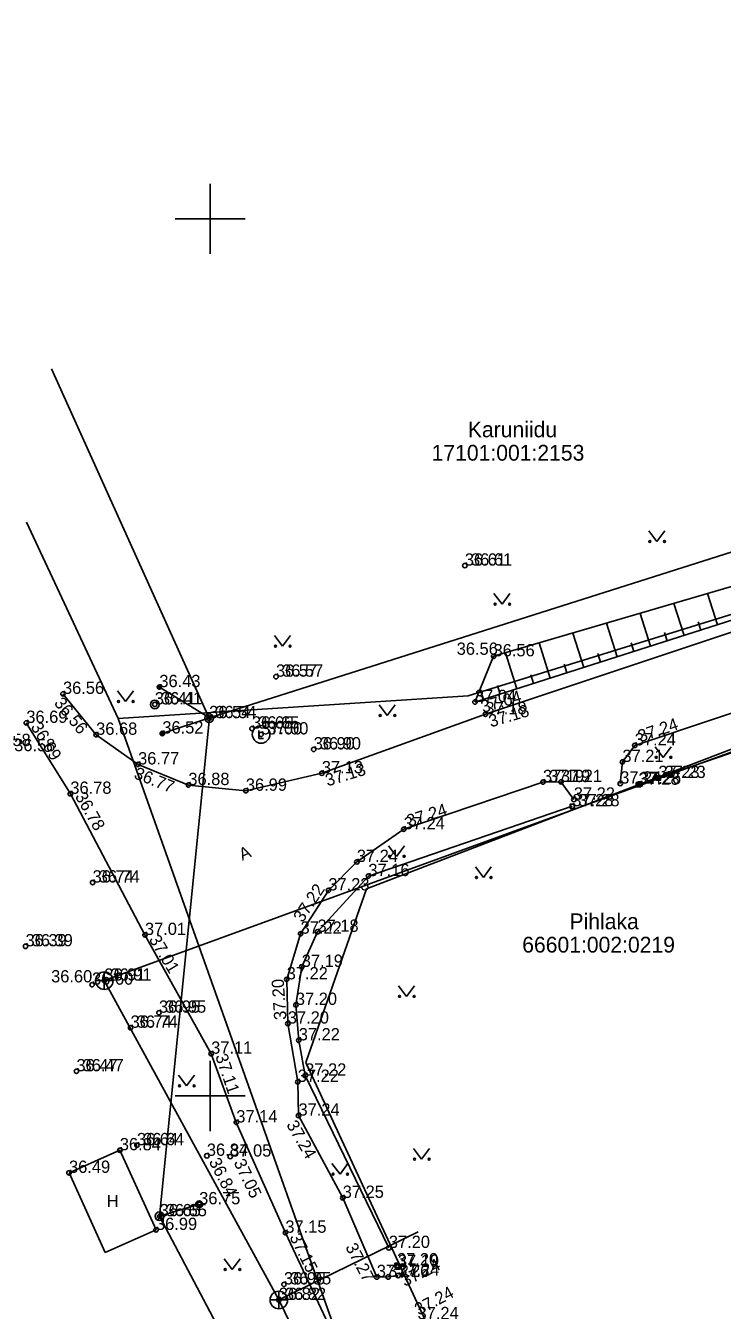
# Model space of a CAD drawing. Extents: x 627548 to 628052, y 6467984 to 6468802.
# Drawn here: x 627639.5 to 627679.2, y 6468387.8 to 6468461 of the extents above; entities that cross this region are included whole.
import ezdxf

# ---------------------------------------------------------------- set-up
doc = ezdxf.new("R2010")
doc.units = 0
for name, color, linetype in [('AED', 7, 'Continuous'), ('HALJASTUS', 7, 'Continuous'), ('KAEV', 7, 'Continuous'), ('KKAEV', 7, 'Continuous'), ('KORGUS-EH2000', 7, 'Continuous'), ('KTRASS', 7, 'Continuous'), ('MOOTKORG-EH2000', 7, 'Continuous'), ('MOOTMPUNKT', 7, 'Continuous'), ('MPOHULIIN', 7, 'Continuous'), ('PIIR', 7, 'Continuous'), ('POST', 7, 'Continuous'), ('RAJATIS', 7, 'Continuous'), ('RELJEEF', 7, 'Continuous'), ('SIOHULIIN', 7, 'Continuous'), ('TEE', 7, 'Continuous'), ('VORK', 7, 'Continuous')]:
    doc.layers.add(name, color=color, linetype=linetype)

msp = doc.modelspace()

# ---------------------------------------------------------------- linework, layer by layer
at = {"layer": 'AED'}
for p, q in [((627674.27, 6468417.863), (627674.27, 6468417.613)), ((627674.27, 6468417.863), (627674.52, 6468417.863)), ((627674.357, 6468417.911), (627674.357, 6468417.661)), ((627674.357, 6468417.911), (627674.607, 6468417.911)), ((627674.52, 6468417.863), (627674.52, 6468417.613)), ((627674.607, 6468417.911), (627674.607, 6468417.661)), ((627675.406, 6468418.249), (627675.406, 6468417.999)), ((627675.406, 6468418.249), (627675.656, 6468418.249)), ((627675.406, 6468417.999), (627675.656, 6468417.999)), ((627675.656, 6468418.249), (627675.656, 6468417.999)), ((627674.27, 6468417.613), (627674.52, 6468417.613)), ((627674.357, 6468417.661), (627674.607, 6468417.661)), ((627670.5, 6468416.637), (627670.5, 6468416.387)), ((627670.5, 6468416.637), (627670.75, 6468416.637)), ((627670.5, 6468416.387), (627670.75, 6468416.387)), ((627670.75, 6468416.637), (627670.75, 6468416.387)), ((627660.516, 6468390.467), (627660.516, 6468390.217)), ((627660.516, 6468390.467), (627660.766, 6468390.467)), ((627660.516, 6468390.217), (627660.766, 6468390.217)), ((627660.568, 6468390.378), (627660.568, 6468390.128)), ((627660.568, 6468390.378), (627660.818, 6468390.378)), ((627660.568, 6468390.128), (627660.818, 6468390.128)), ((627660.766, 6468390.467), (627660.766, 6468390.217)), ((627660.818, 6468390.378), (627660.818, 6468390.128))]:
    msp.add_line(p, q, dxfattribs=at)
for points in [[(627699.286, 6468421.733), (627697.85, 6468425.664), (627684.125, 6468421.07), (627675.531, 6468418.124)], [(627670.625, 6468416.512), (627659.01, 6468412.531), (627656.111, 6468409.355), (627655.215, 6468407.357), (627654.88, 6468405.188), (627655.043, 6468403.167), (627655.409, 6468401.157), (627660.175, 6468391.332)]]:
    msp.add_lwpolyline(points, dxfattribs=at)
at = {"layer": 'HALJASTUS'}
for p, q in [((627674.982, 6468432.212), (627675.445, 6468431.605)), ((627675.445, 6468431.605), (627675.891, 6468432.212)), ((627666.165, 6468428.636), (627666.628, 6468428.029)), ((627666.628, 6468428.029), (627667.074, 6468428.636)), ((627653.655, 6468426.252), (627654.118, 6468425.645)), ((627654.118, 6468425.645), (627654.564, 6468426.252)), ((627644.719, 6468423.093), (627645.182, 6468422.486)), ((627645.182, 6468422.486), (627645.628, 6468423.093)), ((627659.621, 6468422.293), (627660.084, 6468421.686)), ((627660.084, 6468421.686), (627660.53, 6468422.293)), ((627675.348, 6468419.909), (627675.811, 6468419.302)), ((627675.811, 6468419.302), (627676.257, 6468419.909)), ((627660.156, 6468414.265), (627660.619, 6468413.658)), ((627660.619, 6468413.658), (627661.064, 6468414.265)), ((627665.104, 6468413.054), (627665.567, 6468412.447)), ((627665.567, 6468412.447), (627666.013, 6468413.054)), ((627660.725, 6468406.283), (627661.188, 6468405.676)), ((627661.188, 6468405.676), (627661.634, 6468406.283)), ((627648.193, 6468401.183), (627648.656, 6468400.576)), ((627648.656, 6468400.576), (627649.102, 6468401.183)), ((627661.578, 6468397.008), (627662.041, 6468396.401)), ((627662.041, 6468396.401), (627662.487, 6468397.008)), ((627656.934, 6468396.144), (627657.397, 6468395.537)), ((627657.397, 6468395.537), (627657.843, 6468396.144)), ((627650.792, 6468390.714), (627651.256, 6468390.107)), ((627651.256, 6468390.107), (627651.701, 6468390.714))]:
    msp.add_line(p, q, dxfattribs=at)
for centre in [(627675.044, 6468431.605), (627675.873, 6468431.605), (627666.227, 6468428.029), (627667.056, 6468428.029), (627653.717, 6468425.645), (627654.546, 6468425.645), (627644.781, 6468422.486), (627645.61, 6468422.486), (627659.683, 6468421.686), (627660.512, 6468421.686), (627675.41, 6468419.302), (627676.239, 6468419.302), (627660.218, 6468413.658), (627661.047, 6468413.658), (627665.166, 6468412.447), (627665.995, 6468412.447), (627660.787, 6468405.676), (627661.616, 6468405.676), (627648.255, 6468400.576), (627649.084, 6468400.576), (627661.64, 6468396.401), (627662.469, 6468396.401), (627656.996, 6468395.537), (627657.825, 6468395.537), (627650.855, 6468390.107), (627651.683, 6468390.107)]:
    msp.add_circle(centre, 0.055, dxfattribs=at)
at = {"layer": 'KAEV'}
for p, q in [((627652.769, 6468420.834), (627652.769, 6468420.384)), ((627652.769, 6468420.384), (627653.027, 6468420.384))]:
    msp.add_line(p, q, dxfattribs=at)
msp.add_circle((627652.898, 6468420.609), 0.5, dxfattribs=at)
at = {"layer": 'KKAEV'}
for p, q in [((627643.967, 6468406.071), (627643.967, 6468407.071)), ((627643.467, 6468406.571), (627644.467, 6468406.571)), ((627653.907, 6468387.868), (627653.907, 6468388.868)), ((627653.407, 6468388.368), (627654.407, 6468388.368))]:
    msp.add_line(p, q, dxfattribs=at)
for centre in [(627643.967, 6468406.571), (627653.907, 6468388.368)]:
    msp.add_circle(centre, 0.5, dxfattribs=at)
at = {"layer": 'KTRASS'}
for points in [[(627653.907, 6468388.368), (627643.967, 6468406.571), (627696.734, 6468425.803), (627727.929, 6468434.638), (627765.976, 6468446.513), (627766.878, 6468443.315), (627768.149, 6468438.807)], [(627669.837, 6468355.594), (627653.907, 6468388.368), (627661.842, 6468392.243)]]:
    msp.add_lwpolyline(points, dxfattribs=at)
at = {"layer": 'MOOTMPUNKT'}
for centre in [(627664.503, 6468430.232), (627666.141, 6468425.06), (627653.747, 6468423.9), (627641.613, 6468422.918), (627647.103, 6468423.305), (627646.844, 6468422.319), (627665.082, 6468422.456), (627649.939, 6468421.535), (627665.677, 6468421.76), (627639.524, 6468421.265), (627643.502, 6468420.588), (627647.272, 6468420.66), (627652.378, 6468420.942), (627652.898, 6468420.609), (627674.185, 6468419.981), (627655.894, 6468419.753), (627645.892, 6468418.897), (627656.357, 6468418.393), (627673.482, 6468419.039), (627648.756, 6468417.722), (627668.955, 6468417.89), (627669.976, 6468417.9), (627673.355, 6468417.806), (627674.395, 6468417.738), (627674.482, 6468417.786), (627675.531, 6468418.124), (627642.033, 6468417.224), (627652.03, 6468417.397), (627670.625, 6468416.512), (627670.712, 6468416.891), (627661.021, 6468415.201), (627658.351, 6468413.337), (627659.01, 6468412.531), (627643.3, 6468412.165), (627656.73, 6468411.715), (627646.281, 6468409.175), (627655.147, 6468409.247), (627656.111, 6468409.355), (627639.481, 6468408.528), (627655.215, 6468407.357), (627643.271, 6468406.341), (627643.967, 6468406.571), (627654.357, 6468406.644), (627647.079, 6468404.744), (627654.88, 6468405.188), (627645.461, 6468403.886), (627654.421, 6468404.123), (627655.043, 6468403.167), (627650.055, 6468402.405), (627642.38, 6468401.404), (627655.409, 6468401.157), (627654.986, 6468400.8), (627655.028, 6468398.877), (627651.487, 6468398.488), (627645.827, 6468397.19), (627644.85, 6468396.901), (627649.807, 6468396.584), (627651.139, 6468396.541), (627641.957, 6468395.613), (627649.371, 6468393.822), (627657.549, 6468394.188), (627647.118, 6468393.14), (627646.912, 6468392.358), (627654.281, 6468392.2), (627660.175, 6468391.332), (627660.641, 6468390.342), (627660.693, 6468390.253), (627654.2, 6468389.254), (627659.49, 6468389.674), (627660.136, 6468389.678), (627660.706, 6468389.759), (627653.907, 6468388.368)]:
    msp.add_circle(centre, 0.125, dxfattribs=at)
at = {"layer": 'MPOHULIIN'}
msp.add_line((627649.939, 6468421.535), (627640.956, 6468441.442), dxfattribs=at)
for points in [[(627697.787, 6468436.749), (627649.965, 6468421.549)], [(627649.965, 6468421.549), (627647.118, 6468393.14)], [(627647.118, 6468393.14), (627668.977, 6468351.69)]]:
    msp.add_lwpolyline(points, dxfattribs=at)
at = {"layer": 'PIIR'}
for p, q in [((627644.75, 6468421.52), (627639.527, 6468432.704)), ((627696.02, 6468432.54), (627664.7, 6468422.8)), ((627658.9, 6468411.81), (627697.47, 6468426.57)), ((627664.7, 6468422.8), (627644.75, 6468421.52)), ((627664.45, 6468365.98), (627644.75, 6468421.52)), ((627655.45, 6468401.9), (627658.9, 6468411.81)), ((627668.1, 6468374.6), (627655.45, 6468401.9))]:
    msp.add_line(p, q, dxfattribs=at)
at = {"layer": 'POST'}
for points in [[(627647.103, 6468423.305), (627649.965, 6468421.549)], [(627647.272, 6468420.66), (627649.965, 6468421.549)], [(627649.371, 6468393.822), (627647.118, 6468393.14)]]:
    msp.add_lwpolyline(points, dxfattribs=at)
for centre, radius in [((627647.103, 6468423.305), 0.125), ((627647.103, 6468423.305), 0.117), ((627647.103, 6468423.305), 0.109), ((627647.103, 6468423.305), 0.102), ((627647.103, 6468423.305), 0.0938), ((627647.103, 6468423.305), 0.086), ((627647.103, 6468423.305), 0.0782), ((627647.103, 6468423.305), 0.0704), ((627647.103, 6468423.305), 0.0626), ((627647.103, 6468423.305), 0.0548), ((627647.103, 6468423.305), 0.047), ((627647.103, 6468423.305), 0.0392), ((627647.103, 6468423.305), 0.0314), ((627647.103, 6468423.305), 0.0236), ((627647.103, 6468423.305), 0.0158), ((627647.103, 6468423.305), 0.00798), ((627647.103, 6468423.305), 0.000186), ((627649.939, 6468421.535), 0.25), ((627649.939, 6468421.535), 0.0234), ((627647.272, 6468420.66), 0.125), ((627647.272, 6468420.66), 0.117), ((627647.272, 6468420.66), 0.109), ((627647.272, 6468420.66), 0.102), ((627647.272, 6468420.66), 0.0938), ((627647.272, 6468420.66), 0.086), ((627647.272, 6468420.66), 0.0782), ((627647.272, 6468420.66), 0.0704), ((627647.272, 6468420.66), 0.0626), ((627647.272, 6468420.66), 0.0548), ((627647.272, 6468420.66), 0.047), ((627647.272, 6468420.66), 0.0392), ((627647.272, 6468420.66), 0.0314), ((627647.272, 6468420.66), 0.0236), ((627647.272, 6468420.66), 0.0158), ((627647.272, 6468420.66), 0.00798), ((627647.272, 6468420.66), 0.000186), ((627649.371, 6468393.822), 0.2), ((627647.118, 6468393.14), 0.25), ((627647.118, 6468393.14), 0.0234)]:
    msp.add_circle(centre, radius, dxfattribs=at)
at = {"layer": 'RAJATIS'}
for points in [[(627646.912, 6468392.358), (627644.85, 6468396.901), (627641.957, 6468395.613)], [(627644.019, 6468391.07), (627641.957, 6468395.613)], [(627646.912, 6468392.358), (627644.019, 6468391.07)]]:
    msp.add_lwpolyline(points, dxfattribs=at)
msp.add_circle((627646.844, 6468422.319), 0.25, dxfattribs=at)
at = {"layer": 'RELJEEF'}
for p, q in [((627676.991, 6468426.255), (627676.411, 6468428.072)), ((627678.896, 6468426.863), (627678.331, 6468428.635)), ((627675.085, 6468425.647), (627674.491, 6468427.509)), ((627673.18, 6468425.039), (627672.572, 6468426.946)), ((627677.943, 6468426.559), (627677.791, 6468427.035)), ((627671.275, 6468424.432), (627670.652, 6468426.383)), ((627676.038, 6468425.951), (627675.886, 6468426.428)), ((627667.464, 6468423.216), (627666.813, 6468425.257)), ((627669.369, 6468423.824), (627668.732, 6468425.82)), ((627672.227, 6468424.735), (627672.075, 6468425.212)), ((627674.133, 6468425.343), (627673.981, 6468425.82)), ((627670.322, 6468424.128), (627670.17, 6468424.604)), ((627668.416, 6468423.52), (627668.264, 6468423.996)), ((627665.558, 6468422.608), (627665.376, 6468423.179)), ((627666.511, 6468422.912), (627666.359, 6468423.388))]:
    msp.add_line(p, q, dxfattribs=at)
for points in [[(627696.651, 6468435.326), (627694.06, 6468434.488), (627681.566, 6468429.584), (627666.141, 6468425.06), (627665.082, 6468422.456)], [(627665.082, 6468422.456), (627682.037, 6468427.865), (627695.156, 6468431.738), (627696.486, 6468433.552), (627696.651, 6468435.326)]]:
    msp.add_lwpolyline(points, dxfattribs=at)
at = {"layer": 'SIOHULIIN'}
for points in [[(627697.787, 6468436.749), (627649.965, 6468421.549)], [(627649.965, 6468421.549), (627647.118, 6468393.14)], [(627647.118, 6468393.14), (627668.977, 6468351.69)]]:
    msp.add_lwpolyline(points, dxfattribs=at)
at = {"layer": 'TEE'}
for points in [[(627796.263, 6468461.011), (627787.58, 6468457.698), (627775.784, 6468453.617), (627755.708, 6468445.797), (627743.362, 6468441.806), (627728.433, 6468436.983), (627717.465, 6468433.665), (627699.12, 6468428.233), (627696.098, 6468427.452), (627683.485, 6468423.1), (627674.185, 6468419.981), (627673.482, 6468419.039), (627673.355, 6468417.806)], [(627641.613, 6468422.918), (627643.502, 6468420.588), (627645.892, 6468418.897), (627648.756, 6468417.722), (627652.03, 6468417.397), (627656.357, 6468418.393), (627665.677, 6468421.76), (627682.248, 6468427.296), (627694.979, 6468431.122), (627698.392, 6468432.085), (627706.02, 6468434.537), (627706.299, 6468441.373)], [(627664.163, 6468372.339), (627656.73, 6468386.978), (627654.281, 6468392.2), (627651.487, 6468398.488), (627650.055, 6468402.405), (627646.281, 6468409.175), (627642.033, 6468417.224), (627639.524, 6468421.265)], [(627670.712, 6468416.891), (627669.976, 6468417.9), (627668.955, 6468417.89), (627661.021, 6468415.201), (627658.351, 6468413.337), (627656.73, 6468411.715), (627655.147, 6468409.247), (627654.357, 6468406.644), (627654.421, 6468404.123), (627654.986, 6468400.8), (627655.028, 6468398.877), (627657.549, 6468394.188), (627659.49, 6468389.674), (627660.136, 6468389.678), (627660.706, 6468389.759)]]:
    msp.add_lwpolyline(points, dxfattribs=at)
at = {"layer": 'VORK'}
for p, q in [((627650, 6468452), (627650, 6468448)), ((627648, 6468450), (627652, 6468450)), ((627650, 6468402), (627650, 6468398)), ((627648, 6468400), (627652, 6468400))]:
    msp.add_line(p, q, dxfattribs=at)

# ---------------------------------------------------------------- texts
at = {"layer": 'KORGUS-EH2000'}
for s, p in [('36.61', (627664.853, 6468430.232)), ('36.56', (627664.04, 6468425.147)), ('36.57', (627654.097, 6468423.9)), ('36.41', (627647.194, 6468422.319)), ('36.54', (627650.289, 6468421.535)), ('36.65', (627652.728, 6468420.942)), ('37.00', (627653.248, 6468420.609)), ('36.58', (627637.432, 6468419.944)), ('36.90', (627656.244, 6468419.753)), ('37.19', (627669.305, 6468417.89)), ('37.23', (627675.881, 6468418.124)), ('37.28', (627670.975, 6468416.512)), ('36.74', (627643.65, 6468412.165)), ('36.39', (627639.831, 6468408.528)), ('36.60', (627640.937, 6468406.473)), ('36.91', (627644.317, 6468406.571)), ('36.95', (627647.429, 6468404.744)), ('36.74', (627645.811, 6468403.886)), ('36.47', (627642.73, 6468401.404)), ('36.64', (627646.177, 6468397.19)), ('36.65', (627647.468, 6468393.14)), ('36.95', (627654.55, 6468389.254)), ('36.82', (627654.257, 6468388.368))]:
    msp.add_text(s, height=0.7, dxfattribs=at).set_placement(p)
for s, rotation, p in [('37.04', 15.91524, (627665.534, 6468421.829)), ('36.56', 309.02293, (627641.069, 6468422.379)), ('37.18', 16.5702, (627665.986, 6468421.004)), ('37.24', 18.86178, (627674.502, 6468420.154)), ('36.69', 301.77481, (627639.749, 6468421.039)), ('36.77', 338.0953, (627645.607, 6468418.128)), ('37.13', 16.95418, (627656.682, 6468417.641)), ('36.78', 299.91933, (627642.277, 6468417.078)), ('37.24', 17.62131, (627661.322, 6468415.323)), ('37.22', 56.32945, (627655.262, 6468409.841)), ('37.01', 300.8901, (627646.486, 6468408.927)), ('37.20', 93.94425, (627654.346, 6468404.357)), ('37.11', 288.73916, (627650.28, 6468402.271)), ('37.24', 299.94121, (627654.315, 6468398.364)), ('36.84', 297.02911, (627649.905, 6468396.256)), ('37.05', 295.55336, (627651.322, 6468396.212)), ('37.15', 296.22375, (627654.498, 6468391.962)), ('37.27', 297.47723, (627657.682, 6468391.393)), ('37.24', 26.08953, (627661.081, 6468389.11)), ('37.24', 28.01154, (627661.879, 6468387.468))]:
    msp.add_text(s, height=0.7, rotation=rotation, dxfattribs=at).set_placement(p)
at = {"layer": 'MOOTKORG-EH2000'}
for s, p in [('36.61', (627664.503, 6468430.232)), ('36.56', (627666.141, 6468425.06)), ('36.57', (627653.747, 6468423.9)), ('36.43', (627647.103, 6468423.305)), ('36.56', (627641.613, 6468422.918)), ('36.41', (627646.844, 6468422.319)), ('37.04', (627665.082, 6468422.456)), ('36.54', (627649.939, 6468421.535)), ('37.18', (627665.677, 6468421.76)), ('36.69', (627639.524, 6468421.265)), ('36.65', (627652.378, 6468420.942)), ('36.68', (627643.502, 6468420.588)), ('36.52', (627647.272, 6468420.66)), ('37.00', (627652.898, 6468420.609)), ('36.58', (627638.833, 6468419.652)), ('36.90', (627655.894, 6468419.753)), ('37.24', (627674.185, 6468419.981)), ('36.77', (627645.892, 6468418.897)), ('37.21', (627673.482, 6468419.039)), ('37.13', (627656.357, 6468418.393)), ('37.19', (627668.955, 6468417.89)), ('37.21', (627669.976, 6468417.9)), ('37.24', (627673.355, 6468417.806)), ('37.23', (627675.531, 6468418.124)), ('36.78', (627642.033, 6468417.224)), ('36.88', (627648.756, 6468417.722)), ('36.99', (627652.03, 6468417.397)), ('37.28', (627674.395, 6468417.738)), ('37.26', (627674.482, 6468417.786)), ('37.28', (627670.625, 6468416.512)), ('37.22', (627670.712, 6468416.891)), ('37.24', (627661.021, 6468415.201)), ('37.24', (627658.351, 6468413.337)), ('36.74', (627643.3, 6468412.165)), ('37.16', (627659.01, 6468412.531)), ('37.23', (627656.73, 6468411.715)), ('37.01', (627646.281, 6468409.175)), ('37.22', (627655.147, 6468409.247)), ('37.18', (627656.111, 6468409.355)), ('36.39', (627639.481, 6468408.528)), ('37.19', (627655.215, 6468407.357)), ('36.60', (627643.271, 6468406.341)), ('36.91', (627643.967, 6468406.571)), ('37.22', (627654.357, 6468406.644)), ('36.95', (627647.079, 6468404.744)), ('37.20', (627654.88, 6468405.188)), ('36.74', (627645.461, 6468403.886)), ('37.20', (627654.421, 6468404.123)), ('37.22', (627655.043, 6468403.167)), ('37.11', (627650.055, 6468402.405)), ('36.47', (627642.38, 6468401.404)), ('37.22', (627655.409, 6468401.157)), ('37.22', (627654.986, 6468400.8)), ('37.24', (627655.028, 6468398.877)), ('37.14', (627651.487, 6468398.488)), ('36.84', (627644.85, 6468396.901)), ('36.64', (627645.827, 6468397.19)), ('36.84', (627649.807, 6468396.584)), ('37.05', (627651.139, 6468396.541)), ('36.49', (627641.957, 6468395.613)), ('36.75', (627649.371, 6468393.822)), ('37.25', (627657.549, 6468394.188)), ('36.65', (627647.118, 6468393.14)), ('36.99', (627646.912, 6468392.358)), ('37.15', (627654.281, 6468392.2)), ('37.20', (627660.175, 6468391.332)), ('37.20', (627660.641, 6468390.342)), ('37.19', (627660.693, 6468390.253)), ('36.95', (627654.2, 6468389.254)), ('37.27', (627659.49, 6468389.674)), ('37.26', (627660.136, 6468389.678)), ('37.24', (627660.706, 6468389.759)), ('36.82', (627653.907, 6468388.368)), ('37.24', (627661.81, 6468387.273))]:
    msp.add_text(s, height=0.7, dxfattribs=at).set_placement(p)
at = {"layer": 'PIIR'}
for s, p in [('Karuniidu', (627664.676, 6468437.546)), ('17101:001:2153', (627662.612, 6468436.215)), ('Pihlaka', (627670.466, 6468409.503)), ('66601:002:0219', (627667.773, 6468408.173))]:
    msp.add_text(s, height=0.9, dxfattribs=at).set_placement(p)
at = {"layer": 'RAJATIS'}
msp.add_text('H', height=0.7, dxfattribs=at).set_placement((627644.108, 6468393.66))
at = {"layer": 'TEE'}
msp.add_text('A', height=0.7, rotation=23.80727, dxfattribs=at).set_placement((627651.827, 6468413.407))

doc.saveas('drawing.dxf')
